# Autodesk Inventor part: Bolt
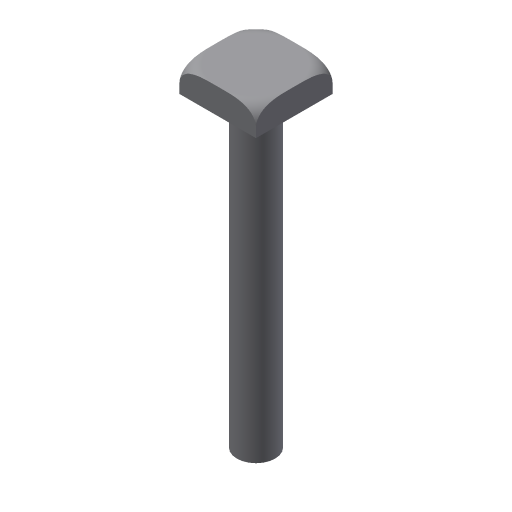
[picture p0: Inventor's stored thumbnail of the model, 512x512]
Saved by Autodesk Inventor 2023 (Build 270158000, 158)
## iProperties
Created: 2009-04
Part Number: Bolt
Document SubType Name: Modeling
Designer: Sham
Density: 1 g/cm^3
Material: Generic
Appearance: Default
Author: Sham
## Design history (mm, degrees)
sketch "Sketch1"
  geometry: L1 (-12, 12)-(12, 12); L2 (12, 12)-(12, -12); L3 (12, -12)-(-12, -12); L4 (-12, -12)-(-12, 12); 1 further point
  constraints: 8 end point, 2 parallel, 2 perpendicular, 1 horizontal, 1 other
  dimensions: "d0" = 24 distance of L1.start L1.end; "d1" = 12 distance from line of L2 point (0, 0); "d2" = 12 distance from line of L1 point (0, 0)
extrude "Extrusion1" new body sketch "Sketch1" distance "d3" = 8; taper "d4" = 0 deg
sketch "Sketch2"
  geometry: C1 r 6 at (0, 0)
  constraints: 1 centre point
  dimensions: "d5" = 12 diameter of C1
extrude "Extrusion2" join sketch "Sketch2" distance "d6" = 96; taper "d7" = 0 deg
workpoint "Work Point1"
workplane "Work Plane1"
sketch "Sketch3"
  geometry: L1 (33.941, 5)-(33.941, 6); L2 (28.941, 0)-(28.405, 0); L3 (16.971, 125.007)-(16.971, -22.043) reference; A1 r 5 centre (28.941, 5) between (28.941, 0) and (33.941, 5); 1 further point
  constraints: 4 end point, 2 point on circle, 2 point on line, 2 tangent, 1 centre point, 1 perpendicular
  dimensions: "d10" = 5 radius of A1
revolve "Revolution1" sketch "Sketch3" stored, may be unused: angle "d12" = 90 deg
body "Solid1"
other parameters: "d11" = 90 deg
